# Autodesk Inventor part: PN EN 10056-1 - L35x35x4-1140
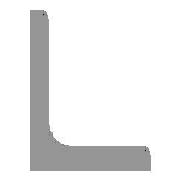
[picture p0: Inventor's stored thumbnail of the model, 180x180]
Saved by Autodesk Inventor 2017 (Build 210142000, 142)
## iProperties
Created: 2020-07
Part Number: PN EN 10056-1 - L35x35x4-1140
Material: Stal, miękka
Description: Kątownik równoramienny
Document SubType Name: Modeling
Standard: PN
Designer: X
Standards Organization: PN
Language: pl-PL
Size Designation: L35x35x4
Categories: <MemberInstance><Categories><Category DisplayName="Kształtowniki konstrukcyjne" InternalName="089c4875-fa83-4c05-b084-43b9cc11f5ed" Mnemonic="GRDR"><CategoryPar
Stock Number: L35x35x4
Density: 7.85 g/cm^3
Appearance: Częściowo polerowana
IsCustomPart: 1
_CCFamilyMember: 60
_CCFamilyDisplayName: PN EN 10056-1 (Kątownik równoramienny) - Kątownik równoramienny
_FrameMemberDoc: Frame Member File
_Version: 15.0.0
_GetPNFromCC: 1
Author: X
G_L: 1140,000 mm
G_W: 35,000 mm
G_H: 35,000 mm
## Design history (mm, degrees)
node "Płaszczyzna początkowa"
node "Płaszczyzna końcowa"
sketch "Szkic"
  geometry: L1 (-6.019, -1.019)-(-6.019, 22.481); L2 (-10.019, 24.981)-(-8.519, 24.981); L3 (-10.019, -10.019)-(-10.019, 24.981); L4 (-10.019, -10.019)-(24.981, -10.019); L5 (24.981, -8.519)-(24.981, -10.019); L6 (-1.019, -6.019)-(22.481, -6.019); L7 (0, 32.602)-(0, -17.123) reference; L8 (-17.123, 0)-(32.602, 0) reference; A1 r 5 centre (-1.019, -1.019) between (-6.019, -1.019) and (-1.019, -6.019); A2 r 2.5 centre (-8.519, 22.481) between (-6.019, 22.481) and (-8.519, 24.981); A3 r 2.5 centre (22.481, -8.519) between (24.981, -8.519) and (22.481, -6.019); 3 further points
  constraints: 12 end point, 6 point on circle, 6 point on line, 6 tangent, 3 centre point, 3 horizontal, 3 vertical, 1 equal radius
  dimensions: "d4" = 35 distance of L3.start L4.end (= b); "d6" = 35 distance of L3.start L2.start (= b); "d8" = 4 distance of point (24.981, -6.019) L4.end (= ParT); "d10" = 4 distance of L2.start point (-6.019, 24.981) (= ParT); "d17" = 5 radius of A1 (= R); "d18" = 2.5 radius of A2 (= R1); "d19" = 10.01931 distance between parallel lines of L8 L4 (= ex); "d20" = 10.01931 distance between parallel lines of L3 L7 (= d19)
extrude "Bryła" new body sketch "Szkic" stored distance "d11" = 1140 (= G_L); taper "d12" = 0 deg
node "Driven Length"
  sketch "Sketch3"
    geometry: L1 (0, 0)-(10, 0) reference
    constraints: 2 end point, 1 horizontal
  workplane "Work Plane10"
  sketch "Sketch4"
    geometry: L1 (-2, 0)-(12, 0) reference; L2 (-2, 1140)-(12, 1140) reference
    dimensions: "d24" = 1140 distance between parallel lines of L1 L2 (derived)
body "Solid1"
other parameters: "b" = 35 [user parameter; used in 3 equation terms], "ParT" = 4 [user parameter; used in 3 equation terms], "R" = 5 [user parameter; used in 1 equation term], "R1" = 2.5 [user parameter; used in 1 equation term], "G_L" = 1140 (= d24) [user parameter; used in 1 equation term], "d7" = 4 (derived), "d9" = 4 (derived), "ex" = 10.01931 (computed from b, ParT) [user parameter; used in 1 equation term], "G_OFFSET_START" = 0 [user parameter; used in 1 equation term], "G_OFFSET_END" = 0 [user parameter; used in 1 equation term], "d21" = 0 (computed from G_OFFSET_START), "d23" = 90 deg
